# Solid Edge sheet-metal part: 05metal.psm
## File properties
Author: User
Template: Iso Metric Sheet Metal.psm
Last saved by: User
Revision: 19
Application: Solid Edge
Accuracy: 0,990
Material Thickness: 0,25 mm
Bend Radius: 1,00 mm
Relief Width: 1,00 mm
Relief Length: 0,00 mm
Neutral Factor: 0,330
Minimum Arc Length: 0,10 mm
Deviational Tolerance: 0,10 mm
Username: User
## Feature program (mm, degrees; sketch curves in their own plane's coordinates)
base tab "unnamed BaseTab 1"
dimple "Dimple_2"
louver "Louver_1"  LouverDepth = 1.25 mm; LouverHeight = 1 mm
pattern "unnamed Pattern 1" of "Louver_1"
louver "unnamed Louver 1"
louver "unnamed Louver 2"
louver "unnamed Louver 3"
louver "unnamed Louver 4"
louver "unnamed Louver 5"
louver "unnamed Louver 6"
louver "unnamed Louver 7"
louver "unnamed Louver 8"
louver "unnamed Louver 9"
louver "unnamed Louver 10"
louver "unnamed Louver 11"
mirror "unnamed Mirror 1" of "Louver_1", "unnamed Pattern 1" about plane through (0, 0, 0) normal (1, 0, 0)
louver "unnamed Louver 12"
louver "unnamed Louver 13"
louver "unnamed Louver 14"
louver "unnamed Louver 15"
louver "unnamed Louver 16"
louver "unnamed Louver 17"
louver "unnamed Louver 18"
louver "unnamed Louver 19"
louver "unnamed Louver 20"
louver "unnamed Louver 21"
louver "unnamed Louver 22"
louver "unnamed Louver 23"
bead "Bead_2"
sketch for "unnamed Cutout 1" plane through (0, 0, 0) normal (0, 0, -1) x-axis (1, 0, 0)
  line (0, 0) -> (0, 0)
  line (0, 0) -> (0, 0)
  line (-12.5, 7.5) -> (-12.5, -7.5)
  line (-12.5, -7.5) -> (12.5, -7.5)
  line (12.5, -7.5) -> (12.5, 7.5)
  line (12.5, 7.5) -> (-12.5, 7.5)
extrude "unnamed Cutout 1" cut
flange "Flange_11"
sketch for "unnamed Cutout 2" #1 plane through (0, 0, 1) normal (0, 0, 1) x-axis (1, 0, 0)
  circle centre (2.69, -5.1071) radius 0.125
  dimension (linear) = 2.69
sketch for "unnamed Cutout 2" #2 plane through (0, 0, 1) normal (0, 0, 1) x-axis (1, 0, 0)
  circle centre (-2.69, -5.1071) radius 0.125
extrude "unnamed Cutout 2" cut
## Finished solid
Body 1: solid body, 117 faces, 299 edges, 182 vertices.
  Faces by surface: plane 45, cylinder 32, sphere 32, cone 4, torus 4
  Edges by curve: line 147, circle 144, ellipse 8
Bounding box of the edges (mm; curved faces can reach further): 25.000 x 15.000 x 4.000, from (-12.5, -7.5, -2) to (12.5, 7.5, 2).
Cylindrical faces by radius (mm): R0.125 x2, R0.25 x12, R1 x1, R1.0312 x8, R1.25 x1, R1.2812 x6, R1.2813 x2
Conical faces (half-angle, radius in mm at the cone's reference point): 15 deg R0.0754 x1, 15 deg R0.1591 x1, 15 deg R0.3168 x1, 15 deg R0.4006 x1
Toroidal faces (ring radius, tube radius in mm): R0.125 r0.25 x2, R0.4006 r0.25 x2
Spherical faces by radius (mm): R1.0312 x16, R1.2812 x12, R1.2813 x4
Planar faces by outward normal: +x 5, +y 11, +z 3, -x 5, -y 12, -z 4, oblique 5
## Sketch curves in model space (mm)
line (-12.5, -7.5, 0) -> (-12.5, 7.5, 0)
line (-12.5, 7.5, 0) -> (12.5, 7.5, 0)
line (12.5, 7.5, 0) -> (12.5, -7.5, 0)
line (12.5, -7.5, 0) -> (-12.5, -7.5, 0)
line (0, 17.1336, 22.4054) -> (0, 17.1336, 34.832)
line (0, 17.1336, 34.832) -> (0, -13.1797, 34.832)
line (0, -13.1797, 34.832) -> (0, -13.1797, 22.4054)
line (0, -13.1797, 22.4054) -> (0, 17.1336, 22.4054)
line (-1.75, -4.4821, 1.75) -> (-1.75, -5.7321, 1.75)
line (1.75, -4.4821, 1.75) -> (1.75, -5.7321, 1.75)
line (3, -4.4821, 1.75) -> (-3, -4.4821, 1.75)
line (-3, -4.4821, 1.75) -> (-3, -5.7321, 1.75)
line (-3, -5.7321, 1.75) -> (3, -5.7321, 1.75)
line (3, -5.7321, 1.75) -> (3, -4.4821, 1.75)
line (1.75, -4.4821, 1) -> (1.75, -5.7321, 1)
line (-1.75, -4.4821, 1) -> (-1.75, -5.7321, 1)
line (-3, -4.4821, 1) -> (-3, -5.7321, 1)
line (-3, -5.7321, 1) -> (3, -5.7321, 1)
line (3, -5.7321, 1) -> (3, -4.4821, 1)
line (3, -4.4821, 1) -> (-3, -4.4821, 1)
line (-1.75, -4.4821, 1) -> (-1.75, -5.7321, 1)
line (1.75, -4.4821, 1) -> (1.75, -5.7321, 1)
line (3, -5.7321, 1) -> (3, -4.4821, 1)
line (3, -4.4821, 1) -> (-3, -4.4821, 1)
line (-3, -4.4821, 1) -> (-3, -5.7321, 1)
line (-3, -5.7321, 1) -> (3, -5.7321, 1)
line (-9.3199, -3.342, 1) -> (-3.3199, -3.342, 1)
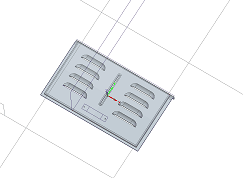
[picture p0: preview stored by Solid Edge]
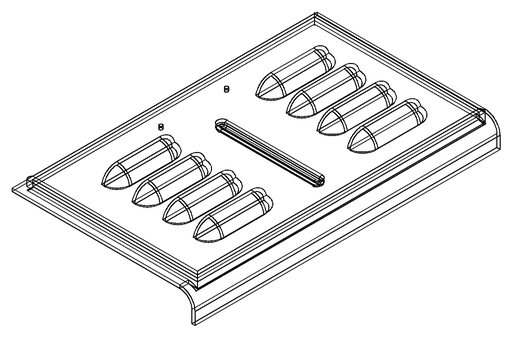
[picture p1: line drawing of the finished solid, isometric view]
